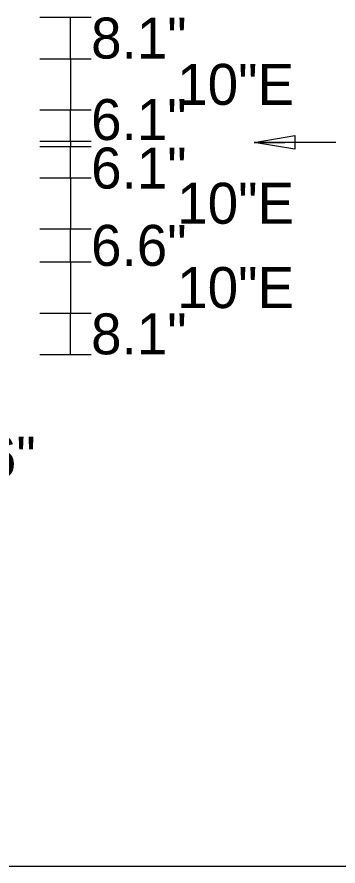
# Model space of a CAD drawing. Extents: x 17890628 to 17890844, y 17897506 to 17897992.
# Drawn here: x 17890755.28 to 17890760.51, y 17897535.26 to 17897549.09 of the extents above; entities that cross this region are included whole.
import ezdxf

# ---------------------------------------------------------------- set-up
doc = ezdxf.new("R2010")
doc.units = 0
doc.layers.add('GSDims', color=7, linetype='Continuous')
doc.layers.add('SheetLinesMisc2_dp', color=7, linetype='Continuous')

msp = doc.modelspace()

# ---------------------------------------------------------------- linework, layer by layer
at = {"layer": 'GSDims'}
for p, q in [((17890755.654, 17897549.08), (17890756.487, 17897549.08)), ((17890756.154, 17897548.404), (17890756.154, 17897549.08)), ((17890755.654, 17897548.404), (17890756.487, 17897548.404)), ((17890755.654, 17897548.404), (17890756.487, 17897548.404)), ((17890756.154, 17897548.404), (17890756.154, 17897547.572)), ((17890755.654, 17897547.572), (17890756.487, 17897547.572)), ((17890755.654, 17897547.572), (17890756.487, 17897547.572)), ((17890756.154, 17897547.062), (17890756.154, 17897547.572)), ((17890755.654, 17897547.062), (17890756.487, 17897547.062)), ((17890755.654, 17897547.062), (17890756.487, 17897547.062)), ((17890756.154, 17897547.062), (17890756.154, 17897546.979)), ((17890759.139, 17897547.042), (17890759.639, 17897547.042)), ((17890760.472, 17897547.042), (17890759.139, 17897547.042)), ((17890755.654, 17897546.979), (17890756.487, 17897546.979)), ((17890755.654, 17897546.979), (17890756.487, 17897546.979)), ((17890756.154, 17897546.469), (17890756.154, 17897546.979)), ((17890755.654, 17897546.469), (17890756.487, 17897546.469)), ((17890755.654, 17897546.469), (17890756.487, 17897546.469)), ((17890756.154, 17897546.469), (17890756.154, 17897545.637)), ((17890755.654, 17897545.637), (17890756.487, 17897545.637)), ((17890755.654, 17897545.637), (17890756.487, 17897545.637)), ((17890756.154, 17897545.096), (17890756.154, 17897545.637)), ((17890755.654, 17897545.096), (17890756.487, 17897545.096)), ((17890755.654, 17897545.096), (17890756.487, 17897545.096)), ((17890756.154, 17897545.096), (17890756.154, 17897544.263)), ((17890755.654, 17897544.263), (17890756.487, 17897544.263)), ((17890755.654, 17897544.263), (17890756.487, 17897544.263)), ((17890756.154, 17897543.587), (17890756.154, 17897544.263)), ((17890755.654, 17897543.587), (17890756.487, 17897543.587))]:
    msp.add_line(p, q, dxfattribs=at)
msp.add_lwpolyline([(17890759.805, 17897546.931), (17890759.139, 17897547.042), (17890759.805, 17897547.153)], close=True, dxfattribs=at)
at = {"layer": 'SheetLinesMisc2_dp'}
msp.add_line((17890726.429, 17897535.26), (17890771.912, 17897535.26), dxfattribs=at)

# ---------------------------------------------------------------- texts
at = {"layer": 'GSDims'}
for s, p in [('8.1"', (17890756.487, 17897548.409)), ('10"E', (17890757.889, 17897547.655)), ('6.1"', (17890756.487, 17897547.082)), ('6.1"', (17890756.487, 17897546.292)), ('10"E', (17890757.889, 17897545.719)), ('6.6"', (17890756.487, 17897545.033)), ('10"E', (17890757.889, 17897544.346)), ('8.1"', (17890756.487, 17897543.592)), ('8.6"', (17890754.031, 17897541.587))]:
    msp.add_text(s, height=0.6667, dxfattribs=at).set_placement(p)

doc.saveas('drawing.dxf')
